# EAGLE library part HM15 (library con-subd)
SUB-D
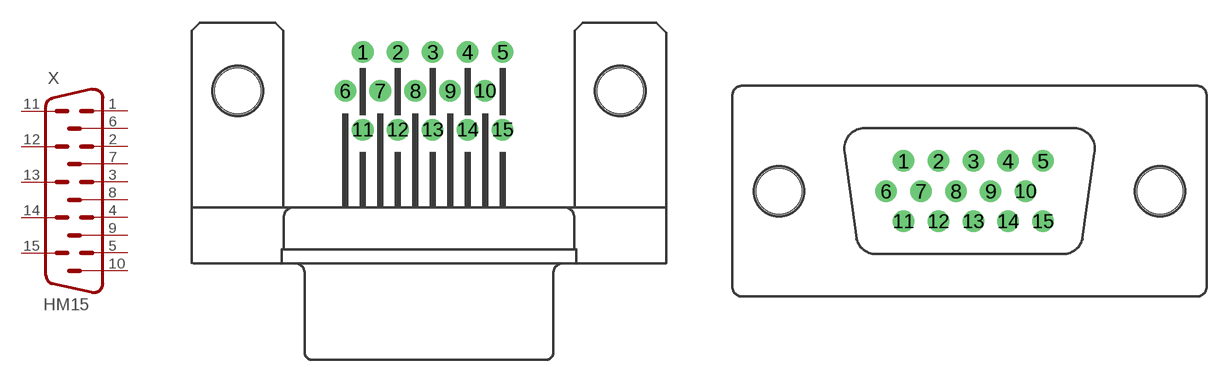
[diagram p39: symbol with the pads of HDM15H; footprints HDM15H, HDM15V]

Designator prefix X

## HM15H (OC_FARNELL: unknown; OC_NEWARK: unknown)  [HDM15H]
1  1  pas
2  2  pas
3  3  pas
4  4  pas
5  5  pas
6  6  pas
7  7  pas
8  8  pas
9  9  pas
10  10  pas
11  11  pas
12  12  pas
13  13  pas
14  14  pas
15  15  pas

## HM15V (OC_FARNELL: unknown; OC_NEWARK: unknown)  [HDM15V]
Pads as for HDM15H

## Footprint HDM15H (pad centres in mm)
SUB-D
drill 0.9 round: 1 -4.329,2.54; 2 -2.043,2.54; 3 0.243,2.54; 4 2.529,2.54; 5 4.815,2.54; 6 -5.472,0; 7 -3.186,0; 8 -0.9,0; 9 1.386,0; 10 3.672,0; 11 -4.329,-2.54; 12 -2.043,-2.54; 13 0.243,-2.54; 14 2.529,-2.54; 15 4.815,-2.54
hole 3 at -12.5,0
hole 3 at 12.5,0

## Footprint HDM15V (pad centres in mm)
SUB-D
drill 0.9 round: 1 -4.324,1.98; 2 -2.038,1.98; 3 0.248,1.98; 4 2.534,1.98; 5 4.82,1.98; 6 -5.467,0; 7 -3.181,0; 8 -0.895,0; 9 1.391,0; 10 3.677,0; 11 -4.324,-1.98; 12 -2.038,-1.98; 13 0.248,-1.98; 14 2.534,-1.98; 15 4.82,-1.98
hole 3 at -12.5,0
hole 3 at 12.5,0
